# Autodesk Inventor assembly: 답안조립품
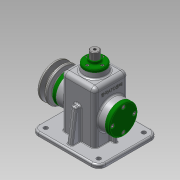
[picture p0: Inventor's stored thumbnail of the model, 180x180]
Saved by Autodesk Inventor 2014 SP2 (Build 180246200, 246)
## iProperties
Created: 2016-08
Part Number: 답안조립품
Document SubType Name: Assembly
Designer: user
Author: user
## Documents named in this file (19)
- C:\Users\user\Desktop\460820V1017\답안조립품.iam
- C:\Users\user\Desktop\460820V1017\본체.ipt
- C:\Users\user\Desktop\460820V1017\V-벨트풀리.ipt
- C:\Users\user\Desktop\460820V1017\고정핀.ipt
- C:\Users\user\Desktop\460820V1017\뒤커버.ipt
- C:\Users\user\Desktop\460820V1017\링크.ipt
- C:\Users\user\Desktop\460820V1017\멈춤링 6 x 5.ipt
- C:\Users\user\Desktop\460820V1017\멈춤링 15 x 1.ipt
- C:\Users\user\Desktop\460820V1017\베어링 15 x 35 x 11.ipt
- C:\Users\user\Desktop\460820V1017\볼트 M3 x 8.ipt
- C:\Users\user\Desktop\460820V1017\볼트 M4 x 10.ipt
- C:\Users\user\Desktop\460820V1017\볼트 M6 x 12.ipt
- C:\Users\user\Desktop\460820V1017\상부부시.ipt
- C:\Users\user\Desktop\460820V1017\슬라이드바.ipt
- C:\Users\user\Desktop\460820V1017\앞커버.ipt
- C:\Users\user\Desktop\460820V1017\오일실 15 25 7.ipt
- C:\Users\user\Desktop\460820V1017\와셔.ipt
- C:\Users\user\Desktop\460820V1017\키 5 x 5 x 14.ipt
- C:\Users\user\Desktop\460820V1017\편심축.ipt
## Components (15 placed, 5 different names)
1. V-벨트풀리:1 — 각도:1
2. 고정핀:1
3. ISO 4018 M6 x 12:1 — 각도:2
4. ISO 4762 M3 x 8:1 — 강체:3
5. ISO 4762 M3 x 8:2
6. ISO 4762 M3 x 8:3
7. ISO 4762 M3 x 8:4
8. ISO 4762 M4 x 10:1 — 강체:2
9. ISO 4762 M4 x 10:3
10. ISO 4762 M4 x 10:4
11. ISO 4762 M4 x 10:5
12. ISO 4762 M4 x 10:2 — 강체:1
13. ISO 4762 M4 x 10:6
14. ISO 4762 M4 x 10:7
15. ISO 4762 M4 x 10:8
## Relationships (5: WeldJoint 3, Angle 2)
- 각도:1 [Angle]: V-벨트풀리:1
- 각도:2 [Angle]: ISO 4018 M6 x 12:1
- 강체:1 [WeldJoint]: ISO 4762 M4 x 10:2
- 강체:2 [WeldJoint]: ISO 4762 M4 x 10:1
- 강체:3 [WeldJoint]: ISO 4762 M3 x 8:1
